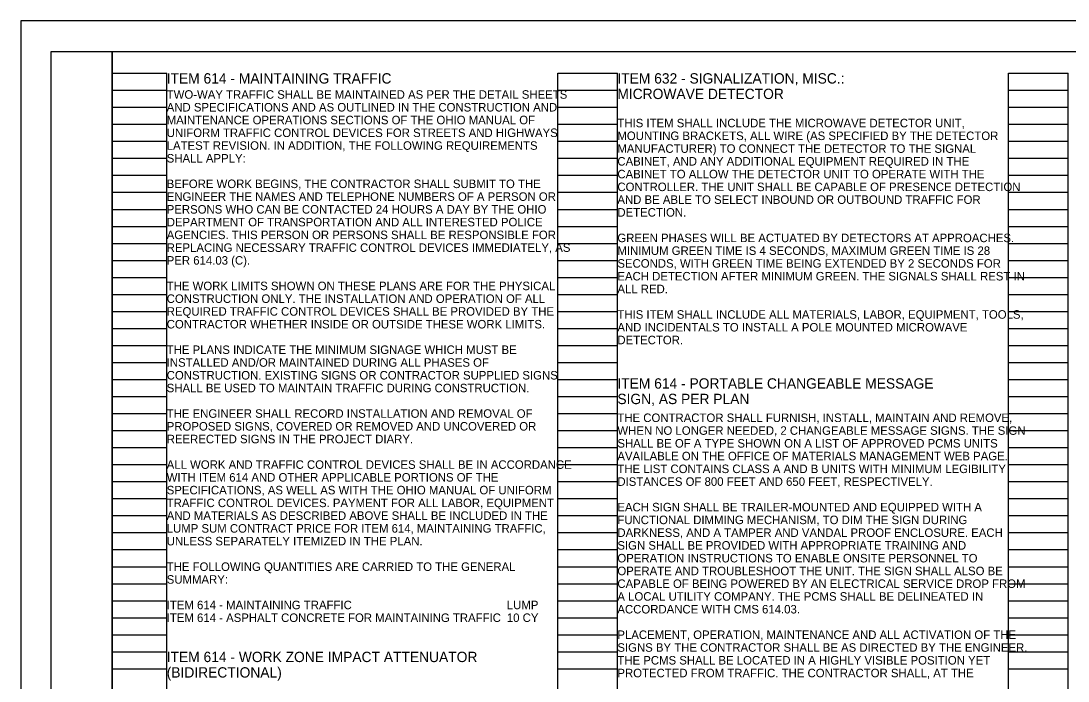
# Model space of a CAD drawing. Extents: x 0 to 34, y 0 to 22.
# Drawn here: x 0 to 17.24, y 11.14 to 22 of the extents above; entities that cross this region are included whole.
import ezdxf

# ---------------------------------------------------------------- set-up
doc = ezdxf.new("R2010")
doc.units = 0
for name, color, linetype in [('SH_Border', 7, 'Continuous'), ('SH_Cut_Line', 7, 'Continuous'), ('SH_Data', 7, 'Continuous'), ('SH_Text', 7, 'Continuous')]:
    doc.layers.add(name, color=color, linetype=linetype)

msp = doc.modelspace()

# ---------------------------------------------------------------- linework, layer by layer
at = {"layer": 'SH_Border'}
for points in [[(0.5, 21.5), (1.5, 21.5), (1.5, 0.5), (0.5, 0.5)], [(1.5, 21.5), (33.5, 21.5), (33.5, 0.5), (1.5, 0.5)]]:
    msp.add_lwpolyline(points, close=True, dxfattribs=at)
at = {"layer": 'SH_Cut_Line'}
msp.add_lwpolyline([(0, 0), (34, 0), (34, 22), (0, 22)], close=True, dxfattribs=at)
at = {"layer": 'SH_Data'}
for p, q in [((1.5, 0.98), (1.5, 21.14)), ((1.5, 21.14), (2.4, 21.14)), ((2.4, 0.98), (2.4, 21.14)), ((8.84, 0.98), (8.84, 21.14)), ((8.84, 21.14), (9.82, 21.14)), ((9.82, 0.98), (9.82, 21.14)), ((16.26, 0.98), (16.26, 21.14)), ((16.26, 21.14), (17.24, 21.14)), ((17.24, 0.98), (17.24, 21.14)), ((1.5, 20.86), (2.4, 20.86)), ((8.84, 20.86), (9.82, 20.86)), ((16.26, 20.86), (17.24, 20.86)), ((1.5, 20.58), (2.4, 20.58)), ((8.84, 20.58), (9.82, 20.58)), ((16.26, 20.58), (17.24, 20.58)), ((1.5, 20.3), (2.4, 20.3)), ((8.84, 20.3), (9.82, 20.3)), ((16.26, 20.3), (17.24, 20.3)), ((1.5, 20.02), (2.4, 20.02)), ((8.84, 20.02), (9.82, 20.02)), ((16.26, 20.02), (17.24, 20.02)), ((1.5, 19.74), (2.4, 19.74)), ((8.84, 19.74), (9.82, 19.74)), ((16.26, 19.74), (17.24, 19.74)), ((1.5, 19.46), (2.4, 19.46)), ((8.84, 19.46), (9.82, 19.46)), ((16.26, 19.46), (17.24, 19.46)), ((1.5, 19.18), (2.4, 19.18)), ((8.84, 19.18), (9.82, 19.18)), ((16.26, 19.18), (17.24, 19.18)), ((1.5, 18.9), (2.4, 18.9)), ((8.84, 18.9), (9.82, 18.9)), ((16.26, 18.9), (17.24, 18.9)), ((1.5, 18.62), (2.4, 18.62)), ((8.84, 18.62), (9.82, 18.62)), ((16.26, 18.62), (17.24, 18.62)), ((1.5, 18.34), (2.4, 18.34)), ((8.84, 18.34), (9.82, 18.34)), ((16.26, 18.34), (17.24, 18.34)), ((1.5, 18.06), (2.4, 18.06)), ((8.84, 18.06), (9.82, 18.06)), ((16.26, 18.06), (17.24, 18.06)), ((1.5, 17.78), (2.4, 17.78)), ((8.84, 17.78), (9.82, 17.78)), ((16.26, 17.78), (17.24, 17.78)), ((1.5, 17.5), (2.4, 17.5)), ((8.84, 17.5), (9.82, 17.5)), ((16.26, 17.5), (17.24, 17.5)), ((1.5, 17.22), (2.4, 17.22)), ((8.84, 17.22), (9.82, 17.22)), ((16.26, 17.22), (17.24, 17.22)), ((1.5, 16.94), (2.4, 16.94)), ((8.84, 16.94), (9.82, 16.94)), ((16.26, 16.94), (17.24, 16.94)), ((1.5, 16.66), (2.4, 16.66)), ((8.84, 16.66), (9.82, 16.66)), ((16.26, 16.66), (17.24, 16.66)), ((1.5, 16.38), (2.4, 16.38)), ((8.84, 16.38), (9.82, 16.38)), ((16.26, 16.38), (17.24, 16.38)), ((1.5, 16.1), (2.4, 16.1)), ((8.84, 16.1), (9.82, 16.1)), ((16.26, 16.1), (17.24, 16.1)), ((1.5, 15.82), (2.4, 15.82)), ((8.84, 15.82), (9.82, 15.82)), ((16.26, 15.82), (17.24, 15.82)), ((1.5, 15.54), (2.4, 15.54)), ((8.84, 15.54), (9.82, 15.54)), ((16.26, 15.54), (17.24, 15.54)), ((1.5, 15.26), (2.4, 15.26)), ((8.84, 15.26), (9.82, 15.26)), ((16.26, 15.26), (17.24, 15.26)), ((1.5, 14.98), (2.4, 14.98)), ((8.84, 14.98), (9.82, 14.98)), ((16.26, 14.98), (17.24, 14.98)), ((1.5, 14.7), (2.4, 14.7)), ((8.84, 14.7), (9.82, 14.7)), ((16.26, 14.7), (17.24, 14.7)), ((1.5, 14.42), (2.4, 14.42)), ((8.84, 14.42), (9.82, 14.42)), ((16.26, 14.42), (17.24, 14.42)), ((1.5, 14.14), (2.4, 14.14)), ((8.84, 14.14), (9.82, 14.14)), ((16.26, 14.14), (17.24, 14.14)), ((1.5, 13.86), (2.4, 13.86)), ((8.84, 13.86), (9.82, 13.86)), ((16.26, 13.86), (17.24, 13.86)), ((1.5, 13.58), (2.4, 13.58)), ((8.84, 13.58), (9.82, 13.58)), ((16.26, 13.58), (17.24, 13.58)), ((1.5, 13.3), (2.4, 13.3)), ((8.84, 13.3), (9.82, 13.3)), ((16.26, 13.3), (17.24, 13.3)), ((1.5, 13.02), (2.4, 13.02)), ((8.84, 13.02), (9.82, 13.02)), ((16.26, 13.02), (17.24, 13.02)), ((1.5, 12.74), (2.4, 12.74)), ((8.84, 12.74), (9.82, 12.74)), ((16.26, 12.74), (17.24, 12.74)), ((1.5, 12.46), (2.4, 12.46)), ((8.84, 12.46), (9.82, 12.46)), ((16.26, 12.46), (17.24, 12.46)), ((1.5, 12.18), (2.4, 12.18)), ((8.84, 12.18), (9.82, 12.18)), ((16.26, 12.18), (17.24, 12.18)), ((1.5, 11.9), (2.4, 11.9)), ((8.84, 11.9), (9.82, 11.9)), ((16.26, 11.9), (17.24, 11.9)), ((1.5, 11.62), (2.4, 11.62)), ((8.84, 11.62), (9.82, 11.62)), ((16.26, 11.62), (17.24, 11.62)), ((1.5, 11.34), (2.4, 11.34)), ((8.84, 11.34), (9.82, 11.34)), ((16.26, 11.34), (17.24, 11.34))]:
    msp.add_line(p, q, dxfattribs=at)

# ---------------------------------------------------------------- texts
at = {"layer": 'SH_Text'}
for s, height, p in [('ITEM 614 - MAINTAINING TRAFFIC', 0.17, (2.4, 20.97)), ('ITEM 632 - SIGNALIZATION, MISC.:', 0.17, (9.82, 20.97)), ('TWO-WAY TRAFFIC SHALL BE MAINTAINED AS PER THE DETAIL SHEETS ', 0.14, (2.4, 20.72)), ('MICROWAVE DETECTOR', 0.17, (9.82, 20.715)), ('AND SPECIFICATIONS AND AS OUTLINED IN THE CONSTRUCTION AND ', 0.14, (2.4, 20.51)), ('MAINTENANCE OPERATIONS SECTIONS OF THE OHIO MANUAL OF ', 0.14, (2.4, 20.3)), ('THIS ITEM SHALL INCLUDE THE MICROWAVE DETECTOR UNIT, ', 0.14, (9.82, 20.25)), ('UNIFORM TRAFFIC CONTROL DEVICES FOR STREETS AND HIGHWAYS ', 0.14, (2.4, 20.09)), ('MOUNTING BRACKETS, ALL WIRE (AS SPECIFIED BY THE DETECTOR ', 0.14, (9.82, 20.04)), ('LATEST REVISION. IN ADDITION, THE FOLLOWING REQUIREMENTS ', 0.14, (2.4, 19.88)), ('MANUFACTURER) TO CONNECT THE DETECTOR TO THE SIGNAL ', 0.14, (9.82, 19.83)), ('SHALL APPLY:', 0.14, (2.4, 19.67)), ('CABINET, AND ANY ADDITIONAL EQUIPMENT REQUIRED IN THE ', 0.14, (9.82, 19.62)), ('CABINET TO ALLOW THE DETECTOR UNIT TO OPERATE WITH THE ', 0.14, (9.82, 19.41)), ('BEFORE WORK BEGINS, THE CONTRACTOR SHALL SUBMIT TO THE ', 0.14, (2.4, 19.25)), ('CONTROLLER. THE UNIT SHALL BE CAPABLE OF PRESENCE DETECTION ', 0.14, (9.82, 19.2)), ('ENGINEER THE NAMES AND TELEPHONE NUMBERS OF A PERSON OR ', 0.14, (2.4, 19.04)), ('PERSONS WHO CAN BE CONTACTED 24 HOURS A DAY BY THE OHIO ', 0.14, (2.4, 18.83)), ('AND BE ABLE TO SELECT INBOUND OR OUTBOUND TRAFFIC FOR ', 0.14, (9.82, 18.99)), ('DETECTION.', 0.14, (9.82, 18.78)), ('DEPARTMENT OF TRANSPORTATION AND ALL INTERESTED POLICE ', 0.14, (2.4, 18.62)), ('AGENCIES. THIS PERSON OR PERSONS SHALL BE RESPONSIBLE FOR ', 0.14, (2.4, 18.41)), ('GREEN PHASES WILL BE ACTUATED BY DETECTORS AT APPROACHES. ', 0.14, (9.82, 18.36)), ('REPLACING NECESSARY TRAFFIC CONTROL DEVICES IMMEDIATELY, AS ', 0.14, (2.4, 18.2)), ('MINIMUM GREEN TIME IS 4 SECONDS, MAXIMUM GREEN TIME IS 28 ', 0.14, (9.82, 18.15)), ('PER 614.03 (C).', 0.14, (2.4, 17.99)), ('SECONDS, WITH GREEN TIME BEING EXTENDED BY 2 SECONDS FOR ', 0.14, (9.82, 17.94)), ('EACH DETECTION AFTER MINIMUM GREEN. THE SIGNALS SHALL REST IN ', 0.14, (9.82, 17.73)), ('THE WORK LIMITS SHOWN ON THESE PLANS ARE FOR THE PHYSICAL ', 0.14, (2.4, 17.57)), ('ALL RED.', 0.14, (9.82, 17.52)), ('CONSTRUCTION ONLY. THE INSTALLATION AND OPERATION OF ALL ', 0.14, (2.4, 17.36)), ('REQUIRED TRAFFIC CONTROL DEVICES SHALL BE PROVIDED BY THE ', 0.14, (2.4, 17.15)), ('THIS ITEM SHALL INCLUDE ALL MATERIALS, LABOR, EQUIPMENT, TOOLS, ', 0.14, (9.82, 17.1)), ('CONTRACTOR WHETHER INSIDE OR OUTSIDE THESE WORK LIMITS.', 0.14, (2.4, 16.94)), ('AND INCIDENTALS TO INSTALL A POLE MOUNTED MICROWAVE ', 0.14, (9.82, 16.89)), ('DETECTOR.', 0.14, (9.82, 16.68)), ('THE PLANS INDICATE THE MINIMUM SIGNAGE WHICH MUST BE ', 0.14, (2.4, 16.52)), ('INSTALLED AND/OR MAINTAINED DURING ALL PHASES OF ', 0.14, (2.4, 16.31)), ('CONSTRUCTION. EXISTING SIGNS OR CONTRACTOR SUPPLIED SIGNS ', 0.14, (2.4, 16.1)), ('ITEM 614 - PORTABLE CHANGEABLE MESSAGE', 0.17, (9.82, 15.95)), ('SHALL BE USED TO MAINTAIN TRAFFIC DURING CONSTRUCTION.', 0.14, (2.4, 15.89)), ('SIGN, AS PER PLAN', 0.17, (9.82, 15.695)), ('THE ENGINEER SHALL RECORD INSTALLATION AND REMOVAL OF ', 0.14, (2.4, 15.47)), ('THE CONTRACTOR SHALL FURNISH, INSTALL, MAINTAIN AND REMOVE, ', 0.14, (9.82, 15.4)), ('PROPOSED SIGNS, COVERED OR REMOVED AND UNCOVERED OR ', 0.14, (2.4, 15.26)), ('REERECTED SIGNS IN THE PROJECT DIARY.', 0.14, (2.4, 15.05)), ('WHEN NO LONGER NEEDED, 2 CHANGEABLE MESSAGE SIGNS. THE SIGN ', 0.14, (9.82, 15.19)), ('SHALL BE OF A TYPE SHOWN ON A LIST OF APPROVED PCMS UNITS ', 0.14, (9.82, 14.98)), ('AVAILABLE ON THE OFFICE OF MATERIALS MANAGEMENT WEB PAGE. ', 0.14, (9.82, 14.77)), ('ALL WORK AND TRAFFIC CONTROL DEVICES SHALL BE IN ACCORDANCE ', 0.14, (2.4, 14.63)), ('THE LIST CONTAINS CLASS A AND B UNITS WITH MINIMUM LEGIBILITY ', 0.14, (9.82, 14.56)), ('WITH ITEM 614 AND OTHER APPLICABLE PORTIONS OF THE ', 0.14, (2.4, 14.42)), ('DISTANCES OF 800 FEET AND 650 FEET, RESPECTIVELY.', 0.14, (9.82, 14.35)), ('SPECIFICATIONS, AS WELL AS WITH THE OHIO MANUAL OF UNIFORM ', 0.14, (2.4, 14.21)), ('TRAFFIC CONTROL DEVICES. PAYMENT FOR ALL LABOR, EQUIPMENT ', 0.14, (2.4, 14)), ('EACH SIGN SHALL BE TRAILER-MOUNTED AND EQUIPPED WITH A ', 0.14, (9.82, 13.93)), ('AND MATERIALS AS DESCRIBED ABOVE SHALL BE INCLUDED IN THE ', 0.14, (2.4, 13.79)), ('FUNCTIONAL DIMMING MECHANISM, TO DIM THE SIGN DURING ', 0.14, (9.82, 13.72)), ('LUMP SUM CONTRACT PRICE FOR ITEM 614, MAINTAINING TRAFFIC, ', 0.14, (2.4, 13.58)), ('DARKNESS, AND A TAMPER AND VANDAL PROOF ENCLOSURE. EACH ', 0.14, (9.82, 13.51)), ('UNLESS SEPARATELY ITEMIZED IN THE PLAN.', 0.14, (2.4, 13.37)), ('SIGN SHALL BE PROVIDED WITH APPROPRIATE TRAINING AND ', 0.14, (9.82, 13.3)), ('OPERATION INSTRUCTIONS TO ENABLE ONSITE PERSONNEL TO ', 0.14, (9.82, 13.09)), ('THE FOLLOWING QUANTITIES ARE CARRIED TO THE GENERAL ', 0.14, (2.4, 12.95)), ('OPERATE AND TROUBLESHOOT THE UNIT. THE SIGN SHALL ALSO BE ', 0.14, (9.82, 12.88)), ('SUMMARY:', 0.14, (2.4, 12.74)), ('CAPABLE OF BEING POWERED BY AN ELECTRICAL SERVICE DROP FROM ', 0.14, (9.82, 12.67)), ('A LOCAL UTILITY COMPANY. THE PCMS SHALL BE DELINEATED IN ', 0.14, (9.82, 12.46)), ('ITEM 614 - MAINTAINING TRAFFIC', 0.14, (2.4, 12.32)), ('LUMP', 0.14, (8, 12.32)), ('ITEM 614 - ASPHALT CONCRETE FOR MAINTAINING TRAFFIC', 0.14, (2.4, 12.11)), ('10 CY', 0.14, (8, 12.11)), ('ACCORDANCE WITH CMS 614.03.', 0.14, (9.82, 12.25)), ('PLACEMENT, OPERATION, MAINTENANCE AND ALL ACTIVATION OF THE ', 0.14, (9.82, 11.83)), ('SIGNS BY THE CONTRACTOR SHALL BE AS DIRECTED BY THE ENGINEER. ', 0.14, (9.82, 11.62)), ('ITEM 614 - WORK ZONE IMPACT ATTENUATOR', 0.17, (2.4, 11.45)), ('THE PCMS SHALL BE LOCATED IN A HIGHLY VISIBLE POSITION YET ', 0.14, (9.82, 11.41)), ('(BIDIRECTIONAL)', 0.17, (2.4, 11.195)), ('PROTECTED FROM TRAFFIC. THE CONTRACTOR SHALL, AT THE ', 0.14, (9.82, 11.2))]:
    msp.add_text(s, height=height, dxfattribs=at).set_placement(p)

doc.saveas('drawing.dxf')
